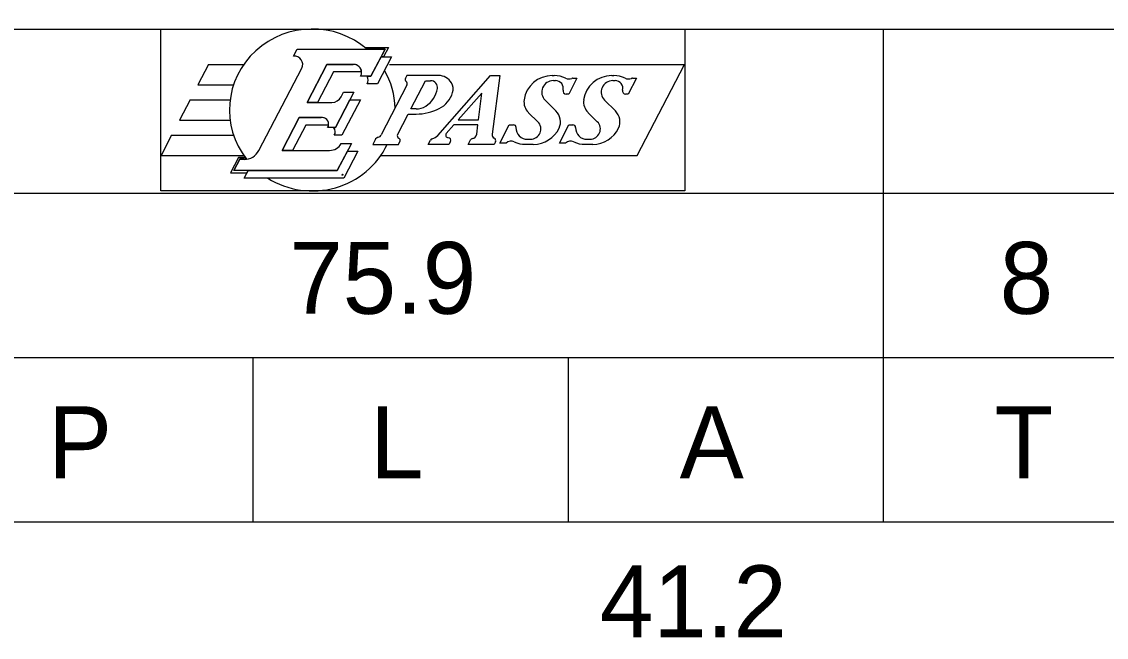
# Model space of a CAD drawing. Extents: x 10268312 to 10268472, y 2142583 to 2142688.
# Drawn here: x 10268404.18 to 10268414.76, y 2142603.11 to 2142609.1 of the extents above; entities that cross this region are included whole.
import ezdxf

# ---------------------------------------------------------------- set-up
doc = ezdxf.new("R2010")
doc.units = 0
for name, color, linetype in [('GSBWFill', 7, 'Continuous'), ('NonPlottingEle_dp', 7, 'Continuous'), ('SumBoxLines_dp', 7, 'Continuous'), ('SumBoxLinesMin_dp', 7, 'Continuous'), ('TextLabel', 7, 'Continuous')]:
    doc.layers.add(name, color=color, linetype=linetype)

msp = doc.modelspace()

# ---------------------------------------------------------------- linework, layer by layer
at = {"layer": 'GSBWFill'}
for p, q in [((10268406.832, 2142608.769), (10268406.867, 2142608.835)), ((10268406.867, 2142608.835), (10268407.725, 2142608.835)), ((10268407.526, 2142608.854), (10268407.757, 2142608.854)), ((10268407.725, 2142608.835), (10268407.587, 2142608.572)), ((10268407.757, 2142608.854), (10268407.709, 2142608.761)), ((10268407.587, 2142608.572), (10268407.686, 2142608.761)), ((10268407.587, 2142608.572), (10268407.686, 2142608.761)), ((10268407.788, 2142608.761), (10268407.651, 2142608.498)), ((10268407.788, 2142608.761), (10268407.651, 2142608.498)), ((10268407.686, 2142608.761), (10268407.788, 2142608.761)), ((10268407.686, 2142608.761), (10268407.788, 2142608.761)), ((10268406.003, 2142608.687), (10268405.9, 2142608.49)), ((10268406.003, 2142608.687), (10268406.347, 2142608.687)), ((10268406.493, 2142607.849), (10268406.912, 2142608.651)), ((10268406.965, 2142608.318), (10268407.158, 2142608.687)), ((10268407.158, 2142608.687), (10268406.965, 2142608.318)), ((10268406.965, 2142608.318), (10268407.158, 2142608.687)), ((10268407.221, 2142608.614), (10268407.067, 2142608.318)), ((10268407.221, 2142608.614), (10268407.067, 2142608.318)), ((10268407.158, 2142608.687), (10268407.415, 2142608.687)), ((10268407.415, 2142608.687), (10268407.158, 2142608.687)), ((10268407.158, 2142608.687), (10268407.415, 2142608.687)), ((10268407.495, 2142608.614), (10268407.221, 2142608.614)), ((10268407.495, 2142608.614), (10268407.221, 2142608.614)), ((10268407.767, 2142608.687), (10268410.646, 2142608.687)), ((10268410.183, 2142607.801), (10268410.646, 2142608.687)), ((10268405.9, 2142608.49), (10268406.248, 2142608.49)), ((10268407.587, 2142608.572), (10268407.486, 2142608.572)), ((10268407.55, 2142608.572), (10268407.587, 2142608.572)), ((10268407.55, 2142608.572), (10268407.587, 2142608.572)), ((10268407.651, 2142608.498), (10268407.55, 2142608.498)), ((10268407.651, 2142608.498), (10268407.55, 2142608.498)), ((10268407.938, 2142608.485), (10268407.688, 2142608.003)), ((10268407.937, 2142608.579), (10268407.923, 2142608.553)), ((10268408.246, 2142608.579), (10268407.937, 2142608.579)), ((10268407.977, 2142608.254), (10268408.12, 2142608.529)), ((10268408.12, 2142608.529), (10268408.168, 2142608.529)), ((10268408.238, 2142607.996), (10268408.754, 2142608.579)), ((10268408.754, 2142608.579), (10268408.845, 2142608.579)), ((10268408.845, 2142608.579), (10268408.769, 2142608.008)), ((10268409.355, 2142608.579), (10268409.374, 2142608.579)), ((10268409.387, 2142608.529), (10268409.366, 2142608.529)), ((10268409.595, 2142608.554), (10268409.515, 2142608.399)), ((10268409.557, 2142608.554), (10268409.595, 2142608.554)), ((10268409.936, 2142608.579), (10268409.955, 2142608.579)), ((10268409.968, 2142608.529), (10268409.946, 2142608.529)), ((10268410.176, 2142608.554), (10268410.096, 2142608.399)), ((10268410.138, 2142608.554), (10268410.176, 2142608.554)), ((10268407.42, 2142608.416), (10268407.24, 2142608.072)), ((10268407.296, 2142608.372), (10268407.319, 2142608.416)), ((10268407.319, 2142608.416), (10268407.42, 2142608.416)), ((10268408.669, 2142608.408), (10268408.439, 2142608.147)), ((10268408.635, 2142608.147), (10268408.669, 2142608.408)), ((10268409.515, 2142608.399), (10268409.49, 2142608.399)), ((10268410.096, 2142608.399), (10268410.07, 2142608.399)), ((10268405.823, 2142608.343), (10268405.72, 2142608.146)), ((10268405.823, 2142608.343), (10268406.214, 2142608.343)), ((10268407.067, 2142608.318), (10268406.965, 2142608.318)), ((10268406.965, 2142608.318), (10268407.206, 2142608.318)), ((10268407.067, 2142608.318), (10268406.965, 2142608.318)), ((10268407.24, 2142608.072), (10268407.382, 2142608.343)), ((10268407.24, 2142608.072), (10268407.382, 2142608.343)), ((10268407.484, 2142608.343), (10268407.304, 2142607.998)), ((10268407.484, 2142608.343), (10268407.304, 2142607.998)), ((10268407.382, 2142608.343), (10268407.484, 2142608.343)), ((10268407.382, 2142608.343), (10268407.484, 2142608.343)), ((10268409.285, 2142608.339), (10268409.391, 2142608.235)), ((10268409.866, 2142608.339), (10268409.971, 2142608.235)), ((10268406.72, 2142607.85), (10268406.888, 2142608.17)), ((10268406.888, 2142608.17), (10268406.72, 2142607.85)), ((10268406.72, 2142607.85), (10268406.888, 2142608.17)), ((10268406.888, 2142608.17), (10268407.1, 2142608.169)), ((10268407.109, 2142608.17), (10268406.888, 2142608.17)), ((10268406.888, 2142608.17), (10268407.1, 2142608.169)), ((10268407.847, 2142608.003), (10268407.951, 2142608.204)), ((10268407.951, 2142608.204), (10268408.027, 2142608.204)), ((10268408.027, 2142608.254), (10268407.977, 2142608.254)), ((10268409.214, 2142608.128), (10268409.123, 2142608.217)), ((10268409.794, 2142608.128), (10268409.704, 2142608.217)), ((10268405.72, 2142608.146), (10268406.214, 2142608.146)), ((10268406.951, 2142608.096), (10268406.822, 2142607.85)), ((10268406.951, 2142608.096), (10268406.822, 2142607.85)), ((10268407.174, 2142608.095), (10268406.951, 2142608.096)), ((10268407.174, 2142608.095), (10268406.951, 2142608.096)), ((10268407.24, 2142608.072), (10268407.164, 2142608.072)), ((10268407.224, 2142608.072), (10268407.24, 2142608.072)), ((10268407.224, 2142608.072), (10268407.24, 2142608.072)), ((10268408.395, 2142608.098), (10268408.322, 2142608.015)), ((10268408.63, 2142608.098), (10268408.395, 2142608.098)), ((10268408.439, 2142608.147), (10268408.635, 2142608.147)), ((10268408.618, 2142608.008), (10268408.63, 2142608.098)), ((10268408.844, 2142607.921), (10268408.936, 2142608.098)), ((10268408.936, 2142608.098), (10268408.977, 2142608.098)), ((10268409.425, 2142607.921), (10268409.516, 2142608.098)), ((10268409.516, 2142608.098), (10268409.557, 2142608.098)), ((10268405.643, 2142607.998), (10268405.54, 2142607.801)), ((10268405.643, 2142607.998), (10268406.248, 2142607.998)), ((10268407.304, 2142607.998), (10268407.228, 2142607.998)), ((10268407.304, 2142607.998), (10268407.228, 2142607.998)), ((10268409.115, 2142607.959), (10268409.143, 2142607.959)), ((10268409.696, 2142607.959), (10268409.723, 2142607.959)), ((10268407.397, 2142607.916), (10268407.259, 2142607.653)), ((10268407.295, 2142607.916), (10268407.397, 2142607.916)), ((10268407.627, 2142607.953), (10268407.604, 2142607.909)), ((10268407.604, 2142607.909), (10268407.856, 2142607.909)), ((10268407.856, 2142607.909), (10268407.87, 2142607.936)), ((10268408.146, 2142607.909), (10268408.168, 2142607.951)), ((10268408.347, 2142607.909), (10268408.146, 2142607.909)), ((10268408.362, 2142607.938), (10268408.347, 2142607.909)), ((10268408.535, 2142607.909), (10268408.557, 2142607.952)), ((10268408.788, 2142607.909), (10268408.535, 2142607.909)), ((10268408.801, 2142607.935), (10268408.788, 2142607.909)), ((10268408.906, 2142607.921), (10268408.844, 2142607.921)), ((10268409.17, 2142607.909), (10268409.094, 2142607.909)), ((10268409.486, 2142607.921), (10268409.425, 2142607.921)), ((10268409.75, 2142607.909), (10268409.674, 2142607.909)), ((10268405.54, 2142607.801), (10268406.347, 2142607.801)), ((10268406.294, 2142607.782), (10268406.217, 2142607.633)), ((10268406.25, 2142607.653), (10268406.307, 2142607.763)), ((10268406.307, 2142607.763), (10268406.25, 2142607.653)), ((10268406.294, 2142607.782), (10268406.36, 2142607.782)), ((10268406.307, 2142607.763), (10268406.349, 2142607.763)), ((10268406.349, 2142607.763), (10268406.307, 2142607.763)), ((10268406.822, 2142607.85), (10268406.72, 2142607.85)), ((10268406.72, 2142607.85), (10268407.184, 2142607.85)), ((10268406.822, 2142607.85), (10268406.72, 2142607.85)), ((10268407.259, 2142607.653), (10268407.358, 2142607.842)), ((10268407.259, 2142607.653), (10268407.358, 2142607.842)), ((10268407.46, 2142607.842), (10268407.322, 2142607.579)), ((10268407.46, 2142607.842), (10268407.322, 2142607.579)), ((10268407.358, 2142607.842), (10268407.46, 2142607.842)), ((10268407.358, 2142607.842), (10268407.46, 2142607.842)), ((10268407.683, 2142607.801), (10268410.183, 2142607.801)), ((10268407.259, 2142607.653), (10268406.25, 2142607.653)), ((10268406.351, 2142607.579), (10268406.389, 2142607.653)), ((10268406.351, 2142607.579), (10268406.389, 2142607.653)), ((10268406.389, 2142607.653), (10268407.259, 2142607.653)), ((10268406.389, 2142607.653), (10268407.259, 2142607.653)), ((10268406.217, 2142607.633), (10268406.379, 2142607.633)), ((10268407.322, 2142607.579), (10268406.351, 2142607.579)), ((10268407.322, 2142607.579), (10268406.351, 2142607.579))]:
    msp.add_line(p, q, dxfattribs=at)
for points in [[(10268407.526, 2142608.854), (10268407.757, 2142608.854), (10268407.709, 2142608.761), (10268407.686, 2142608.761), (10268407.725, 2142608.835), (10268407.549, 2142608.835)], [(10268406.36, 2142607.782), (10268406.294, 2142607.782), (10268406.217, 2142607.633), (10268406.379, 2142607.633), (10268406.389, 2142607.653), (10268406.25, 2142607.653), (10268406.307, 2142607.763), (10268406.349, 2142607.763), (10268406.374, 2142607.765)]]:
    msp.add_lwpolyline(points, close=True, dxfattribs=at)
for centre, major_axis, ratio, start_param, end_param in [((10268407.015, 2142608.244), (0.808, 0), 0.976085, 0.848062, 3.79561), ((10268406.838, 2142608.688), (-0.0833, 0), 0.976085, 2.670351, 4.77879), ((10268407.415, 2142608.609), (-0.0808, 0), 0.976085, 3.204133, 4.712389), ((10268407.415, 2142608.609), (-0.0808, 0), 0.976085, 2.656546, 4.712389), ((10268407.415, 2142608.609), (-0.0808, 0), 0.976085, 3.204133, 4.712389), ((10268407.015, 2142608.244), (0.808, 0), 0.976085, 0.022631, 0.510994), ((10268407.478, 2142608.535), (-0.0808, 0), 0.976085, 2.656546, 3.62876), ((10268407.478, 2142608.535), (-0.0808, 0), 0.976085, 2.656546, 3.62876), ((10268407.946, 2142608.541), (0.0252, 0), 0.983347, 2.669977, 4.034506), ((10268407.911, 2142608.499), (0.0303, 0), 0.983347, 5.811993, 7.176099), ((10268408.168, 2142608.462), (0.0681, 0), 0.983347, 6.127432, 7.853982), ((10268408.246, 2142608.438), (-0.144, 0), 0.983347, 3.655269, 4.712389), ((10268408.262, 2142608.446), (-0.126, 0), 0.983347, 2.874686, 3.655269), ((10268409.355, 2142608.306), (-0.278, 0), 0.983347, 4.712389, 6.148951), ((10268409.366, 2142608.418), (0.114, 0), 0.983347, 1.570796, 3.926991), ((10268409.374, 2142608.331), (-0.252, 0), 0.983347, 4.260167, 4.712389), ((10268409.387, 2142608.455), (0.0757, 0), 0.983347, 6.033455, 7.853982), ((10268409.518, 2142608.621), (-0.0757, 0), 0.983347, 1.118574, 1.955375), ((10268409.557, 2142608.524), (-0.0303, 0), 0.983347, 4.712389, 5.096968), ((10268409.936, 2142608.306), (-0.278, 0), 0.983347, 4.712389, 6.148951), ((10268409.946, 2142608.418), (0.114, 0), 0.983347, 1.570796, 3.926991), ((10268409.955, 2142608.331), (-0.252, 0), 0.983347, 4.260167, 4.712389), ((10268409.968, 2142608.455), (0.0757, 0), 0.983347, 6.033455, 7.853982), ((10268410.098, 2142608.621), (-0.0757, 0), 0.983347, 1.118574, 1.955375), ((10268410.138, 2142608.524), (-0.0303, 0), 0.983347, 4.712389, 5.096968), ((10268407.986, 2142608.491), (0.252, 0), 0.983347, 5.278235, 6.127432), ((10268408.14, 2142608.479), (0.252, 0), 0.983347, 5.1774, 6.016279), ((10268409.49, 2142608.429), (0.0303, 0), 0.983347, 2.891862, 4.712389), ((10268410.07, 2142608.429), (0.0303, 0), 0.983347, 2.891862, 4.712389), ((10268407.206, 2142608.416), (0.101, 0), 0.976085, 4.712389, 5.811742), ((10268408.027, 2142608.428), (0.177, 0), 0.983347, 4.712389, 5.278235), ((10268409.23, 2142608.323), (-0.151, 0), 0.983347, 6.148951, 7.068583), ((10268409.811, 2142608.323), (-0.151, 0), 0.983347, 6.148951, 7.068583), ((10268407.109, 2142608.106), (-0.0656, 0), 0.976085, 2.973171, 4.857851), ((10268407.109, 2142608.106), (-0.0656, 0), 0.976085, 2.973171, 4.857851), ((10268407.109, 2142608.106), (-0.0656, 0), 0.976085, 2.572982, 4.712389), ((10268408.027, 2142608.701), (0.505, 0), 0.983347, 4.712389, 5.1774), ((10268409.284, 2142608.129), (0.151, 0), 0.983347, 5.84598, 7.068583), ((10268409.864, 2142608.129), (0.151, 0), 0.983347, 5.84598, 7.068583), ((10268407.173, 2142608.032), (-0.0656, 0), 0.976085, 2.572982, 3.804466), ((10268407.173, 2142608.032), (-0.0656, 0), 0.976085, 2.572982, 3.804466), ((10268408.977, 2142608.074), (-0.0252, 0), 0.983347, 3.118318, 4.712389), ((10268409.115, 2142608.07), (-0.114, 0), 0.983347, 6.25991, 7.853982), ((10268409.143, 2142608.058), (0.101, 0), 0.983347, 4.712389, 7.068583), ((10268409.17, 2142608.182), (0.278, 0), 0.983347, 4.712389, 5.84598), ((10268409.557, 2142608.074), (-0.0252, 0), 0.983347, 3.118318, 4.712389), ((10268409.696, 2142608.07), (-0.114, 0), 0.983347, 6.25991, 7.853982), ((10268409.723, 2142608.058), (0.101, 0), 0.983347, 4.712389, 7.068583), ((10268409.75, 2142608.182), (0.278, 0), 0.983347, 4.712389, 5.84598), ((10268407.672, 2142607.93), (0.0505, 0), 0.983347, 1.857583, 2.669904), ((10268407.643, 2142608.025), (0.0505, 0), 0.983347, 4.999176, 5.811875), ((10268407.869, 2142607.992), (-0.0252, 0), 0.983347, 5.811744, 7.413866), ((10268407.848, 2142607.947), (-0.0252, 0), 0.983347, 2.670771, 4.272273), ((10268408.19, 2142607.94), (0.0252, 0), 0.983347, 1.792736, 2.670771), ((10268408.162, 2142608.061), (0.101, 0), 0.983347, 4.934329, 5.567541), ((10268408.341, 2142607.999), (-0.0252, 0), 0.983347, 5.567293, 7.831064), ((10268408.34, 2142607.949), (-0.0252, 0), 0.983347, 2.669977, 4.689472), ((10268408.58, 2142607.941), (0.0252, 0), 0.983347, 1.73206, 2.670771), ((10268408.568, 2142608.014), (0.0505, 0), 0.983347, 4.873652, 6.153388), ((10268408.809, 2142608.003), (-0.0404, 0), 0.983347, 6.153828, 7.362974), ((10268408.778, 2142607.946), (-0.0252, 0), 0.983347, 2.669977, 4.221381), ((10268407.015, 2142608.244), (0.808, 0), 0.976085, 4.145825, 5.844223), ((10268407.184, 2142607.973), (0.126, 0), 0.976085, 4.712389, 5.803387), ((10268408.954, 2142607.871), (0.0707, 0), 0.983347, 1.123634, 2.32459), ((10268409.094, 2142608.157), (0.252, 0), 0.983347, 4.265226, 4.712389), ((10268409.534, 2142607.871), (0.0707, 0), 0.983347, 1.123634, 2.32459), ((10268409.674, 2142608.157), (0.252, 0), 0.983347, 4.265226, 4.712389), ((10268406.349, 2142607.92), (0.162, 0), 0.976085, 4.712389, 5.811931)]:
    msp.add_ellipse(centre, major_axis=major_axis, ratio=ratio, start_param=start_param, end_param=end_param, dxfattribs=at)
msp.add_ellipse((10268407.309, 2142607.613), major_axis=(0.00505, 0), ratio=0.976085, dxfattribs=at)
at = {"layer": 'NonPlottingEle_dp'}
msp.add_lwpolyline([(10268405.539, 2142609.032), (10268410.647, 2142609.032), (10268410.647, 2142607.456), (10268405.539, 2142607.456)], close=True, dxfattribs=at)
at = {"layer": 'SumBoxLines_dp'}
for p, q in [((10268395.48, 2142609.032), (10268470.98, 2142609.032)), ((10268395.48, 2142609.032), (10268470.98, 2142609.032)), ((10268412.583, 2142609.032), (10268412.583, 2142607.432)), ((10268412.583, 2142609.032), (10268412.583, 2142607.432)), ((10268412.583, 2142609.032), (10268412.583, 2142604.232)), ((10268395.48, 2142605.832), (10268470.98, 2142605.832)), ((10268406.436, 2142605.832), (10268406.436, 2142604.232)), ((10268406.436, 2142605.832), (10268406.436, 2142604.232)), ((10268409.51, 2142605.832), (10268409.51, 2142604.232)), ((10268409.51, 2142605.832), (10268409.51, 2142604.232)), ((10268411.36, 2142605.832), (10268411.36, 2142605.832)), ((10268411.36, 2142605.832), (10268411.36, 2142605.832)), ((10268412.583, 2142605.832), (10268412.583, 2142604.232))]:
    msp.add_line(p, q, dxfattribs=at)
at = {"layer": 'SumBoxLinesMin_dp'}
for p, q in [((10268395.48, 2142607.432), (10268470.98, 2142607.432)), ((10268395.48, 2142604.232), (10268470.98, 2142604.232))]:
    msp.add_line(p, q, dxfattribs=at)

# ---------------------------------------------------------------- texts
at = {"layer": 'TextLabel'}
for s, p in [('75.9', (10268406.791, 2142606.258)), ('8', (10268413.718, 2142606.258)), ('P', (10268404.438, 2142604.657)), ('L', (10268407.579, 2142604.657)), ('A', (10268410.598, 2142604.657)), ('T', (10268413.669, 2142604.657)), ('41.2', (10268409.82, 2142603.107))]:
    msp.add_text(s, height=0.7, dxfattribs=at).set_placement(p)

doc.saveas('drawing.dxf')
